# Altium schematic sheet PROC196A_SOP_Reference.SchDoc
size 431 x 279 mm; Date: Not shown in title block; ApprovedBy: Not shown in title block; CheckedBy: Not shown in title block; Author: Not shown in title block; CompanyName: Not shown in title block; Engineer: Not shown in title block; Organization: Not shown in title block; Address1: Not shown in title block; Address2: Not shown in title block; Address3: Not shown in title block; Address4: Not shown in title block; DocumentNumber: 8; Revision: Use project parameter SCH_Rev; SheetNumber: 8; SheetTotal: 25; PageSetup: Record=PageOptions¦CenterHorizontal=True¦CenterVertical=True¦PrintScale=1.00¦XCorrection=1.00¦YCorrection=1.00¦PrintKind=0¦BorderSize=5000000¦LeftOffset=0¦BottomOffset=0¦Orientation=2¦PaperLength=1000¦PaperWidth=1000¦Scale=100¦PaperSource=15¦PrintQuality=600¦MediaType=1¦DitherType=10¦PaperKind=Letter¦PrintScaleMode=1
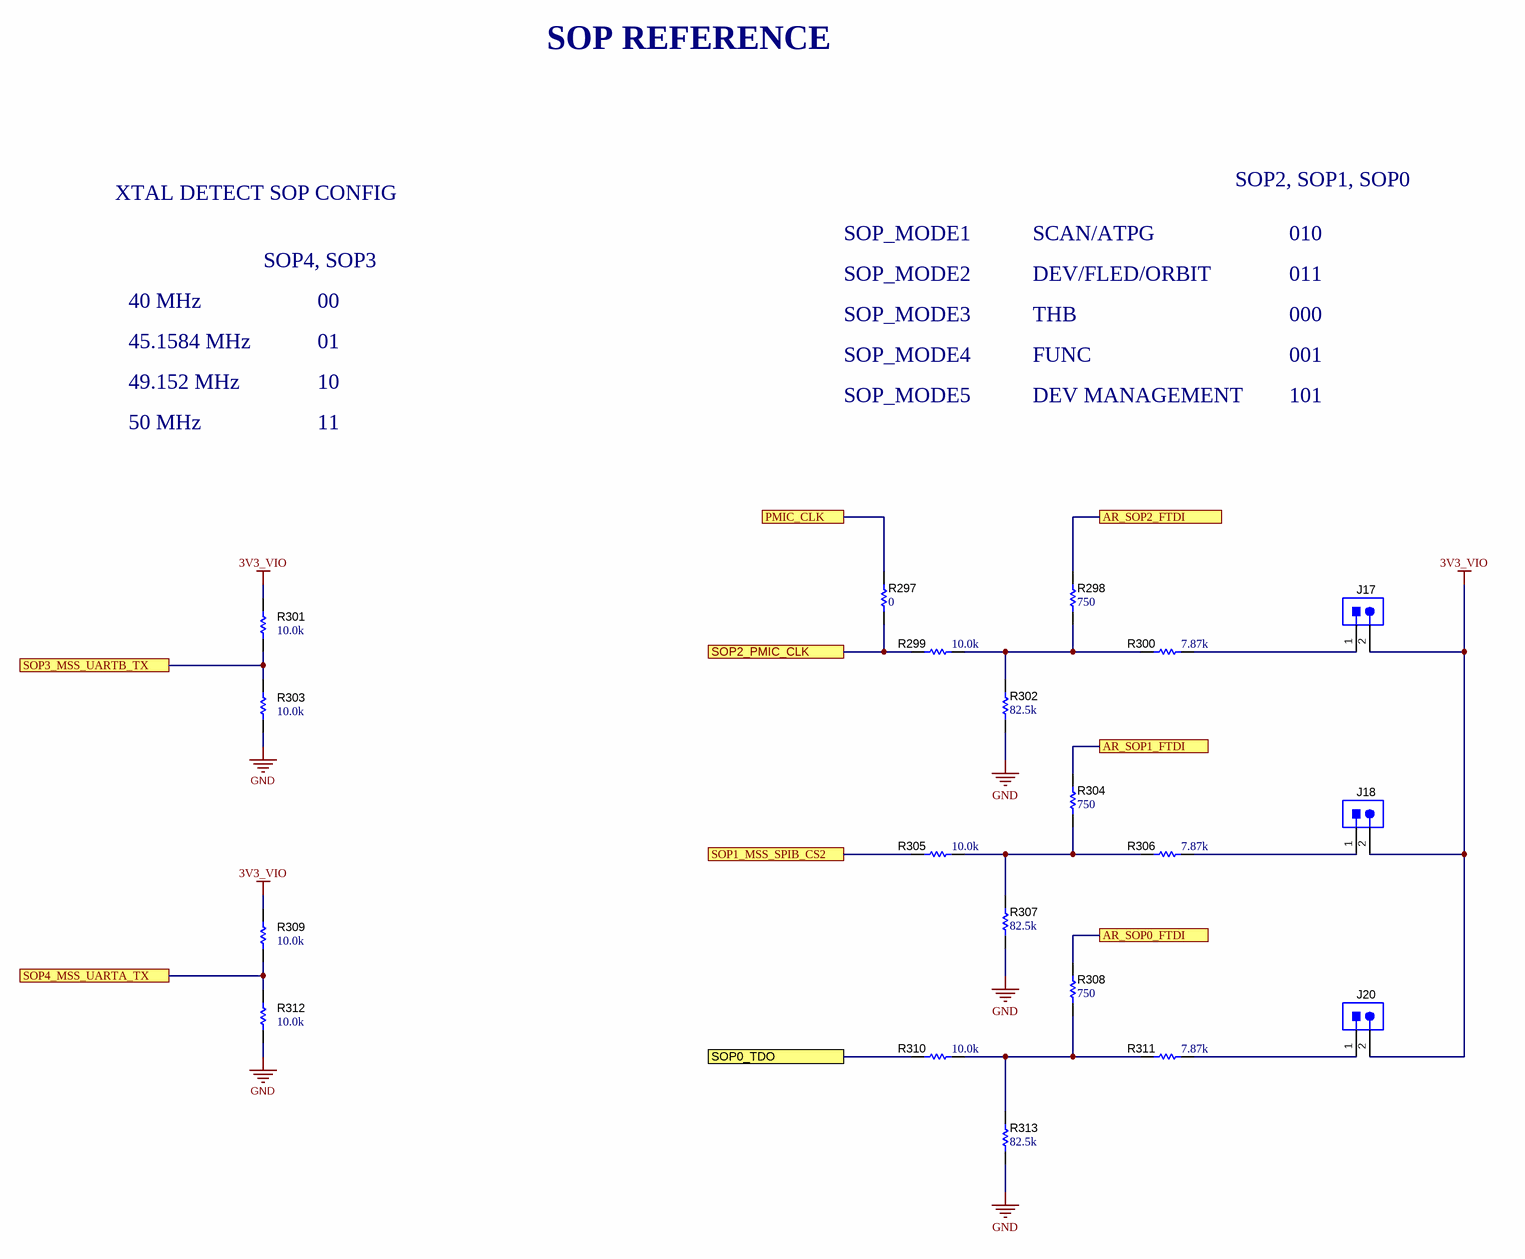
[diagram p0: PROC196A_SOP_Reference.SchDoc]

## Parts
J17  TSW-102-07-G-S  [TSW-102-07-G-S]  (value not drawn)
J18  TSW-102-07-G-S  [TSW-102-07-G-S]  (value not drawn)
J20  TSW-102-07-G-S  [TSW-102-07-G-S]  (value not drawn)
R297  ValueDisplayed: 0  [0402L]  (hidden comment: ERJ-2GE0R00X)
R298  ValueDisplayed: 750  [0402L]  (hidden comment: CRCW0402750RFKED)
R299  ValueDisplayed: 10.0k  [0402L]  (hidden comment: CRCW040210K0FKED)
R300  ValueDisplayed: 7.87k  [0402L]  (hidden comment: CRCW04027K87FKED)
R301  ValueDisplayed: 10.0k  [0402L]  (hidden comment: CRCW040210K0FKED)
R302  ValueDisplayed: 82.5k  [0402L]  (hidden comment: CRCW040282K5FKED)
R303  ValueDisplayed: 10.0k  [0402L]  (hidden comment: CRCW040210K0FKED)
R304  ValueDisplayed: 750  [0402L]  (hidden comment: CRCW0402750RFKED)
R305  ValueDisplayed: 10.0k  [0402L]  (hidden comment: CRCW040210K0FKED)
R306  ValueDisplayed: 7.87k  [0402L]  (hidden comment: CRCW04027K87FKED)
R307  ValueDisplayed: 82.5k  [0402L]  (hidden comment: CRCW040282K5FKED)
R308  ValueDisplayed: 750  [0402L]  (hidden comment: CRCW0402750RFKED)
R309  ValueDisplayed: 10.0k  [0402L]  (hidden comment: CRCW040210K0FKED)
R310  ValueDisplayed: 10.0k  [0402L]  (hidden comment: CRCW040210K0FKED)
R311  ValueDisplayed: 7.87k  [0402L]  (hidden comment: CRCW04027K87FKED)
R312  ValueDisplayed: 10.0k  [0402L]  (hidden comment: CRCW040210K0FKED)
R313  ValueDisplayed: 82.5k  [0402L]  (hidden comment: CRCW040282K5FKED)

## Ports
AR_SOP0_FTDI, AR_SOP1_FTDI, AR_SOP2_FTDI, PMIC_CLK, SOP0_TDO, SOP1_MSS_SPIB_CS2, SOP2_PMIC_CLK, SOP3_MSS_UARTB_TX, SOP4_MSS_UARTA_TX

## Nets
3V3_VIO: J17.2 J18.2 J20.2 R301.2 R309.2
GND: R302.1 R303.1 R307.1 R312.1 R313.1
AR_SOP0_FTDI: R308.2 ; port AR_SOP0_FTDI
AR_SOP1_FTDI: R304.2 ; port AR_SOP1_FTDI
AR_SOP2_FTDI: R298.2 ; port AR_SOP2_FTDI
PMIC_CLK: R297.2 ; port PMIC_CLK
SOP0_TDO: R310.1 ; port SOP0_TDO
SOP1_MSS_SPIB_CS2: R305.1 ; port SOP1_MSS_SPIB_CS2
SOP2_PMIC_CLK: R297.1 R299.1 ; port SOP2_PMIC_CLK
SOP3_MSS_UARTB_TX: R301.1 R303.2 ; port SOP3_MSS_UARTB_TX
SOP4_MSS_UARTA_TX: R309.1 R312.2 ; port SOP4_MSS_UARTA_TX
NetJ17_1: J17.1 R300.2
NetJ18_1: J18.1 R306.2
NetJ20_1: J20.1 R311.2
NetR298_1: R298.1 R299.2 R300.1 R302.2
NetR304_1: R304.1 R305.2 R306.1 R307.2
NetR308_1: R308.1 R310.2 R311.1 R313.2

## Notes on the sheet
- SOP REFERENCE
- XTAL DETECT SOP CONFIG
- SOP2, SOP1, SOP0
- SOP4, SOP3
- SOP_MODE1
- SCAN/ATPG
- 010
- 40 MHz
- 00
- SOP_MODE2
- SOP_MODE3
- DEV/FLED/ORBIT
- THB
- 011
- 000
- 45.1584 MHz
- 49.152 MHz
- 01
- 10
- SOP_MODE4
- SOP_MODE5
- FUNC
- DEV MANAGEMENT
- 001
- 101
- 50 MHz
- 11

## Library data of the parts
J17 J18 J20 = CMP-0075405-3: Header, 100mil, 2x1, Gold, TH; Manufacturer: Samtec; Current_A: 6.3A; Green_Lifecycle: Active; Pitch_mm: 2.54; Cert_CSA: Y; Cert_VDE: N; Green_REACh: Passed; Row_Count: 1; Gender: Male; Voltage_V: 550V
R297 = CMP-0026992-3: RES, 0, 5%, 0.1 W, AEC-Q200 Grade 0, 0402; Manufacturer: Panasonic; Power_W: 100mW; TempCo: 600 ppm/C; Value_Code: 0000; Value: 0; EIA_Code: E24; SizeX_mm: 1; SizeY_mm: 0.5; SizeZ_mm: 0.6; Value2: 0.1W; AEC Qualified: Y; VDC_V: 50V; AEC Category: Q200; SizeAreaWB_mm2: 3
R298 R304 R308 = CMP-0026542-2: RES, 750, 1%, 0.063 W, AEC-Q200 Grade 0, 0402; Manufacturer: Vishay-Dale; Power_W: 63mW; TempCo: 100 ppm/C; Value_Code: 750R; Value: 750; EIA_Code: E96; SizeX_mm: 1; SizeY_mm: 0.5; SizeZ_mm: 0.6; Value2: 0.063W; AEC Qualified: Y; VDC_V: 50V; AEC Grade: 0; AEC Category: Q200
R299 R305 R310 = CMP-0025958-3: RES, 10.0 k, 1%, 0.063 W, AEC-Q200 Grade 0, 0402; Manufacturer: Vishay-Dale; Power_W: 63mW; TempCo: 100 ppm/C; Value_Code: 10k0; Value: 10.0k; EIA_Code: E96; Res_ohm: 10k; SizeX_mm: 1; SizeY_mm: 0.5; SizeZ_mm: 0.6; Value2: 0.063W; AEC Qualified: Y; VDC_V: 50V; AEC Category: Q200; AEC Grade: 0
R300 R306 R311 = CMP-0026557-2: RES, 7.87 k, 1%, 0.063 W, AEC-Q200 Grade 0, 0402; Manufacturer: Vishay-Dale; Power_W: 63mW; TempCo: 100 ppm/C; Value_Code: 7k87; Value: 7.87k; EIA_Code: E96; SizeX_mm: 1; SizeY_mm: 0.5; SizeZ_mm: 0.6; Value2: 0.063W; AEC Qualified: Y; VDC_V: 50V; AEC Grade: 0; AEC Category: Q200
R301 R303 R309 R312 = CMP-0025958-3: RES, 10.0 k, 1%, 0.063 W, AEC-Q200 Grade 0, 0402; Manufacturer: Vishay-Dale; Power_W: 63mW; TempCo: 100 ppm/C; Value_Code: 10k0; Value: 10.0k; EIA_Code: E96; Res_ohm: 10k; SizeX_mm: 1; SizeY_mm: 0.5; SizeZ_mm: 0.6; Value2: 0.063W; CompType: Resistor; AEC Qualified: Y; VDC_V: 50V; AEC Category: Q200; AEC Grade: 0; INSTALLATION: DNP
R302 R307 R313 = CMP-0026574-2: RES, 82.5 k, 1%, 0.063 W, AEC-Q200 Grade 0, 0402; Manufacturer: Vishay-Dale; Power_W: 63mW; TempCo: 100 ppm/C; Value_Code: 82k5; Value: 82.5k; EIA_Code: E96; SizeX_mm: 1; SizeY_mm: 0.5; SizeZ_mm: 0.6; Value2: 0.063W; AEC Qualified: Y; VDC_V: 50V; AEC Grade: 0; AEC Category: Q200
